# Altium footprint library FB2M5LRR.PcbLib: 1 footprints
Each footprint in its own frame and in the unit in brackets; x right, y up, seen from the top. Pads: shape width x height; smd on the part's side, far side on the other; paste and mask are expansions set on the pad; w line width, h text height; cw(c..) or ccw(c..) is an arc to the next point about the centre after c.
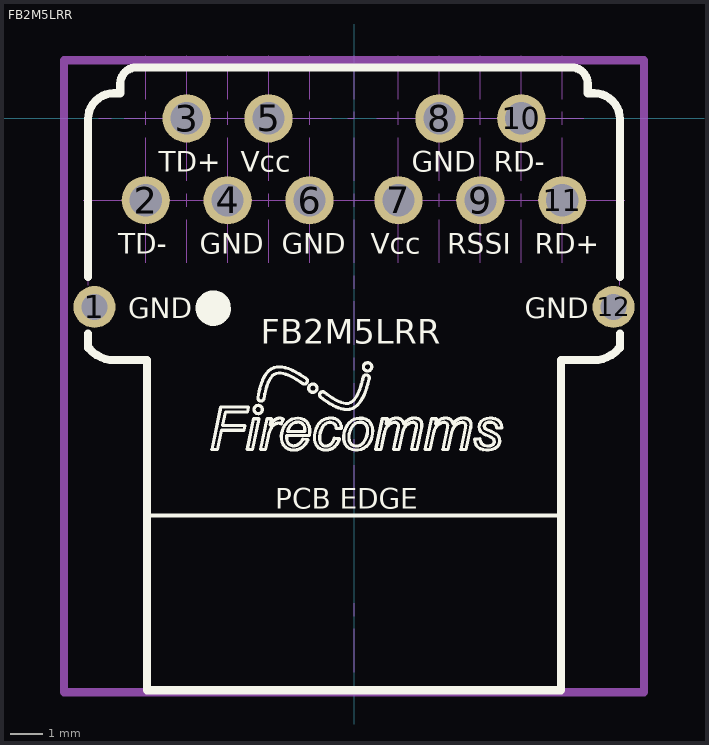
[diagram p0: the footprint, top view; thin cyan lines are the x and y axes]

## FB2M5LRR [mm] "10/100/250 Mbps Fiber Optic  LC Transceiver for 2.2 mm POF"
height 11.8
pads (12):
  round 1.3 hole 0.8: 1(-8.05,-5.85) 12(8.05,-5.85)
  round 1.5 hole 1: 2(-6.46,-2.54) 3(-5.19,0) 4(-3.92,-2.54) 5(-2.65,0) 6(-1.38,-2.54) 7(1.38,-2.54) 8(2.65,0) 9(3.92,-2.54) 10(5.19,0) 11(6.46,-2.54)
Top Overlay:
  drawing of 797 lines, arcs and shapes, not listed
  text "FB2M5LRR" at -2.896,-6.985 h0.76
  text "RD+" at 5.6,-4.2 h0.64
  text "RSSI" at 2.9,-4.2 h0.64
  text "Vcc" at 0.52,-4.2 h0.64
  text "GND" at -2.24,-4.2 h0.64
  text "GND" at -4.78,-4.2 h0.64
  text "TD-" at -7.32,-4.2 h0.64
  text "GND" at 5.3,-6.2 h0.64
  text "GND" at -7,-6.2 h0.64
  text "RD-" at 4.33,-1.66 h0.64
  text "GND" at 1.79,-1.66 h0.64
  text "Vcc" at -3.51,-1.66 h0.64
  text "TD+" at -6.05,-1.66 h0.64
  text "PCB EDGE" at -2.438,-12.116 h0.64
Mechanical 2:
  lines w0.254: -9,-17.8 9,-17.8 9,1.465 9,1.8 5.465,1.8 -9,1.8 -9,-17.8
Mechanical 19:
  drawing of 190 lines, arcs and shapes, not listed
  text "Edge of PCB}" at -5.651,-13.599 h1
3D body "LC Connector Assembly.stp": height 11.8, standoff -3.35, extent -8.25,-17.616 8.25,1.659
